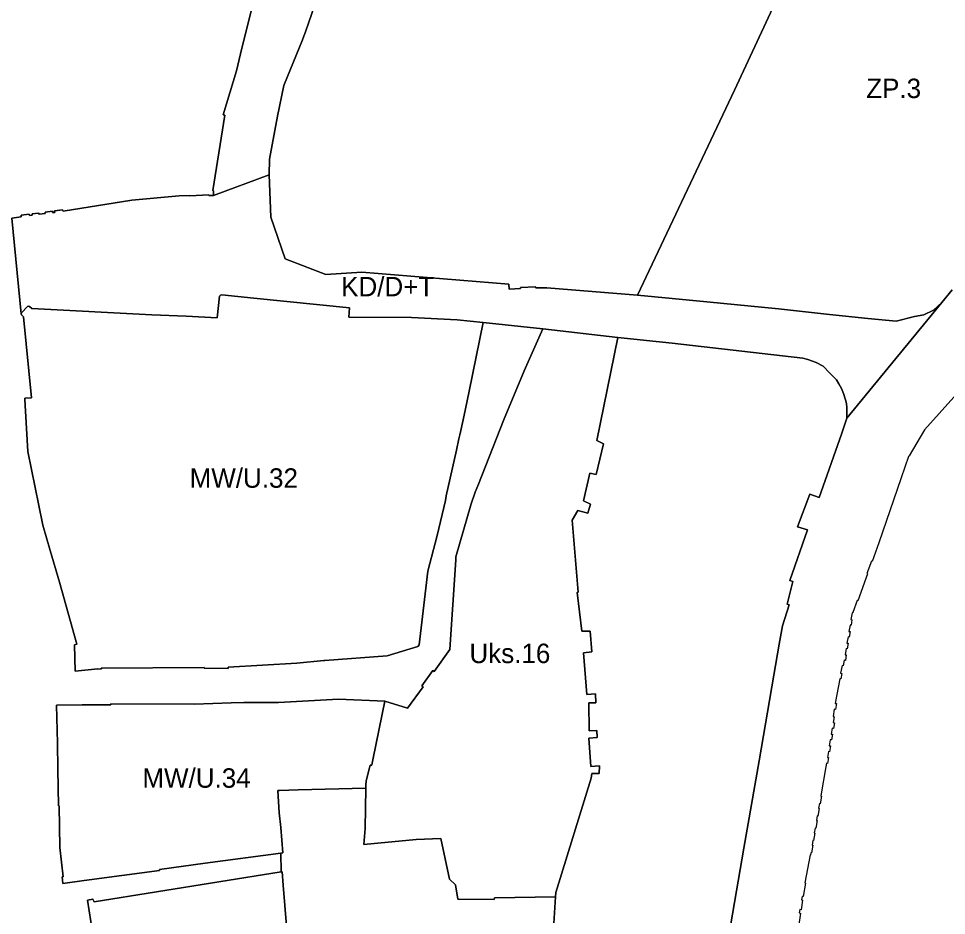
# Model space of a CAD drawing. Extents: x 7423367 to 7424726, y 5546744 to 5548391.
# Drawn here: x 7423955.4 to 7424194.2, y 5547370 to 5547600.8 of the extents above; entities that cross this region are included whole.
import ezdxf

# ---------------------------------------------------------------- set-up
doc = ezdxf.new("R2010")
doc.units = 0
doc.layers.add('linie_rozgraniczajace', color=7, linetype='Continuous')
doc.layers.add('oznaczenia_przeznaczen', color=7, linetype='Continuous')

msp = doc.modelspace()

# ---------------------------------------------------------------- linework, layer by layer
at = {"layer": 'linie_rozgraniczajace'}
for points in [[(7424195.66, 5547530.98), (7424192.95, 5547527.74), (7424190.84, 5547525.79), (7424188.35, 5547524.59), (7424185.9, 5547524.15), (7424181.26, 5547522.91), (7424173.95, 5547523.61), (7424164.06, 5547524.68), (7424150.95, 5547526.11), (7424132.54, 5547527.94), (7424114.69, 5547529.61), (7424122.98, 5547547.25), (7424139.65, 5547582.36), (7424149.46, 5547603.55), (7424164.05, 5547634.41), (7424170.31, 5547647.69), (7424175.4, 5547658.46), (7424181.58, 5547671.67), (7424182.98, 5547674.43), (7424187.08, 5547667.38), (7424194.57, 5547655.72)], [(7424034.47, 5547612.64), (7424029.34, 5547597.71), (7424028.45, 5547595.37), (7424023.69, 5547583.57), (7424022.06, 5547575.71), (7424020.01, 5547564.61), (7424019.9, 5547560.63), (7424005.6, 5547555.3), (7424005.6, 5547556.5), (7424005.44, 5547556.54), (7424008.5, 5547575.97), (7424008.03, 5547576.03), (7424011.47, 5547587.38), (7424012.85, 5547593.23), (7424015.6, 5547604.09)], [(7424149.46, 5547603.55), (7424139.65, 5547582.36), (7424122.98, 5547547.25), (7424114.69, 5547529.61), (7424091.36, 5547531.55), (7424088.52, 5547531.51), (7424088.46, 5547531.79), (7424084.57, 5547531.62), (7424084.6, 5547531.31), (7424081.65, 5547531.19), (7424081.53, 5547532.43), (7424043.78, 5547535.56), (7424034.5, 5547534.91), (7424024.03, 5547538.95), (7424020.34, 5547549.72), (7424019.9, 5547560.63), (7424020.01, 5547564.61), (7424022.06, 5547575.71), (7424023.69, 5547583.57), (7424028.45, 5547595.37), (7424029.34, 5547597.71), (7424034.47, 5547612.64)], [(7424015.6, 5547604.09), (7424012.85, 5547593.23), (7424011.47, 5547587.38), (7424008.03, 5547576.03), (7424008.5, 5547575.97), (7424005.44, 5547556.54), (7424005.6, 5547556.5), (7424005.6, 5547555.3), (7424004.39, 5547555.3), (7424004.38, 5547555.45), (7423999.5, 5547555.18), (7423999.49, 5547555.29), (7423996.74, 5547555.24), (7423984.6, 5547554.11), (7423966.87, 5547551.23), (7423966.76, 5547551.56), (7423964.71, 5547551.31), (7423964.75, 5547550.95), (7423964.17, 5547550.87), (7423964.12, 5547551.22), (7423962.25, 5547550.98), (7423962.29, 5547550.65), (7423960.69, 5547550.44), (7423960.59, 5547550.78), (7423958.88, 5547550.55), (7423958.88, 5547550.2), (7423958.24, 5547550.11), (7423958.15, 5547550.46), (7423956.12, 5547550.19), (7423956.13, 5547549.82), (7423953.67, 5547549.49)], [(7423953.67, 5547549.49), (7423956.05, 5547524.84), (7423956.19, 5547524.54), (7423956.68, 5547524.07), (7423958.72, 5547503.18), (7423958.54, 5547503.18), (7423957.18, 5547503.14), (7423957.03, 5547503.14), (7423957.05, 5547502.74), (7423957.47, 5547495.32), (7423957.8, 5547489.38), (7423961.55, 5547470.88), (7423961.69, 5547470.39), (7423963.52, 5547463.94), (7423965.96, 5547455.79), (7423970.45, 5547439.82), (7423969.78, 5547439.67), (7423970.01, 5547432.86), (7423975.8, 5547433.45), (7423975.8, 5547433.38), (7423976.72, 5547433.46), (7423976.65, 5547433.65), (7424003.15, 5547433.83), (7424003.15, 5547433.63), (7424009.38, 5547433.56), (7424009.37, 5547433.85), (7424027.05, 5547434.91), (7424033.94, 5547435.62), (7424034.18, 5547435.64), (7424050.27, 5547436.84), (7424058.17, 5547439.21), (7424058.48, 5547439.65), (7424060.71, 5547458.62), (7424063.11, 5547467.77), (7424065.23, 5547476.82), (7424065.48, 5547477.95), (7424068.09, 5547489.74), (7424068.74, 5547492.62), (7424068.97, 5547493.65), (7424069.23, 5547494.82), (7424070.07, 5547498.71), (7424070.44, 5547500.39), (7424071.37, 5547504.95), (7424074.96, 5547522.56), (7424090.27, 5547521), (7424085.52, 5547510.17), (7424080.17, 5547497.37), (7424073.72, 5547481.02), (7424072.9, 5547478.96), (7424071.91, 5547475.93), (7424067.96, 5547462.24), (7424067.91, 5547461.55), (7424066.37, 5547438.39), (7424062.33, 5547432.77), (7424062.02, 5547432.99), (7424059.22, 5547429.09), (7424059.48, 5547428.81), (7424055.49, 5547423.29), (7424049.7, 5547425.1), (7424037.73, 5547425.67), (7424022.31, 5547424.81), (7424022.13, 5547424.8), (7424013.42, 5547424.75), (7424010.15, 5547424.73), (7424000.66, 5547424.36), (7423979.15, 5547424.47), (7423979.15, 5547424.22), (7423971.77, 5547424.16), (7423965.22, 5547424.1), (7423965.41, 5547414.3), (7423965.53, 5547407.59), (7423965.7, 5547398.17), (7423965.85, 5547398.17), (7423966.07, 5547387.46), (7423966.88, 5547379.91), (7423966.65, 5547379.91), (7423966.82, 5547378.24), (7423972.3, 5547378.96), (7423991.7, 5547381.53), (7423991.68, 5547381.81), (7424003.43, 5547383.39), (7424022.9, 5547386.01), (7424023.01, 5547381.2), (7423974.87, 5547373.46), (7423974.57, 5547374.13), (7423973.13, 5547373.87), (7423974.91, 5547362.9)], [(7424135.74, 5547350.81), (7424142.07, 5547387.31), (7424145.94, 5547409.81), (7424149.71, 5547431.83), (7424151.1, 5547439.8), (7424151.95, 5547444.55), (7424153.66, 5547449.95), (7424153.17, 5547450.06), (7424154.1, 5547453.83), (7424154.66, 5547455.95), (7424153.82, 5547456.19), (7424158.38, 5547469.22), (7424155.84, 5547470.02), (7424159.03, 5547478.37), (7424161.38, 5547477.58), (7424167.19, 5547493.82), (7424168.25, 5547497.17), (7424168.49, 5547497.94), (7424192.95, 5547527.74), (7424195.66, 5547530.98)], [(7424090.88, 5547332.24), (7424093.59, 5547374.75), (7424093.67, 5547375.89), (7424102.76, 5547405.27), (7424102.96, 5547406.48), (7424104.79, 5547406.48), (7424104.89, 5547408.46), (7424102.68, 5547408.3), (7424102.18, 5547415.64), (7424104.29, 5547415.76), (7424104.21, 5547417.59), (7424102.21, 5547417.49), (7424102.11, 5547424.74), (7424103.94, 5547424.73), (7424103.86, 5547427), (7424101.67, 5547426.83), (7424100.77, 5547437.54), (7424102.88, 5547437.85), (7424102.45, 5547443.16), (7424100.35, 5547443.17), (7424099.12, 5547453.14), (7424099.37, 5547453.18), (7424097.85, 5547471.72), (7424099.28, 5547474.2), (7424101.87, 5547473.53), (7424102.55, 5547475.85), (7424100.77, 5547476.69), (7424102.42, 5547483.79), (7424104.04, 5547483.49), (7424105.88, 5547491.33), (7424104.19, 5547492.25), (7424109.62, 5547518.77), (7424123.56, 5547517.3), (7424157.22, 5547513.42), (7424158.46, 5547513.11), (7424160.68, 5547512.27), (7424162.41, 5547511.32), (7424164.19, 5547509.54), (7424165.84, 5547507.83), (7424166.5, 5547506.78), (7424167.13, 5547505.6), (7424167.66, 5547504.33), (7424168.18, 5547502.73), (7424168.4, 5547501.73), (7424168.51, 5547500.73), (7424168.53, 5547499.53), (7424168.49, 5547497.94), (7424168.25, 5547497.17), (7424167.19, 5547493.82), (7424161.38, 5547477.58), (7424159.03, 5547478.37), (7424155.84, 5547470.02), (7424158.38, 5547469.22), (7424153.82, 5547456.19), (7424154.66, 5547455.95), (7424154.1, 5547453.83), (7424153.17, 5547450.06), (7424153.66, 5547449.95), (7424151.95, 5547444.55), (7424151.1, 5547439.8), (7424149.71, 5547431.83), (7424145.94, 5547409.81), (7424142.07, 5547387.31), (7424135.74, 5547350.81)], [(7424200.59, 5547508.46), (7424188.52, 5547495), (7424184.59, 5547488.28), (7424184.42, 5547488.11), (7424182.5, 5547482.63), (7424176.74, 5547465.86), (7424175.04, 5547461.08), (7424174.84, 5547461.16), (7424173.69, 5547457.97), (7424173.84, 5547457.91), (7424171.36, 5547450.98), (7424171.21, 5547451.03), (7424170.1, 5547447.98), (7424170.07, 5547447.85), (7424169.88, 5547447.88), (7424169.58, 5547446.12), (7424169.85, 5547446.07), (7424169.61, 5547444.65), (7424169.36, 5547444.69), (7424169.08, 5547443.1), (7424169.35, 5547443.05), (7424169.09, 5547441.63), (7424168.83, 5547441.67), (7424168.57, 5547440.1), (7424168.87, 5547440.05), (7424168.64, 5547438.64), (7424168.35, 5547438.69), (7424168.09, 5547437.08), (7424168.38, 5547437.04), (7424168.16, 5547435.61), (7424167.85, 5547435.67), (7424167.59, 5547434.22), (7424167.3, 5547434.28), (7424166.94, 5547432.3), (7424167.2, 5547432.25), (7424166.98, 5547430.86), (7424166.69, 5547430.91), (7424166.37, 5547429.05), (7424165.91, 5547426.38), (7424165.56, 5547424.55), (7424165.85, 5547424.49), (7424165.6, 5547423), (7424165.3, 5547423.05), (7424164.98, 5547421.16), (7424165.29, 5547421.1), (7424165.04, 5547419.64), (7424165.37, 5547419.58), (7424165.11, 5547418.11), (7424164.79, 5547418.17), (7424164.54, 5547416.65), (7424164.85, 5547416.61), (7424164.58, 5547415.14), (7424164.27, 5547415.19), (7424164.02, 5547413.65), (7424164.32, 5547413.6), (7424164.09, 5547412.11), (7424163.79, 5547412.16), (7424163.52, 5547410.64), (7424163.82, 5547410.59), (7424163.58, 5547409.12), (7424163.28, 5547409.18), (7424162.94, 5547407.29), (7424162.01, 5547401.81), (7424161.82, 5547400.71), (7424162.01, 5547400.68), (7424161.67, 5547398.71), (7424161.49, 5547398.75), (7424161.25, 5547397.56), (7424161.45, 5547397.51), (7424161.08, 5547395.56), (7424160.91, 5547395.59), (7424160.7, 5547394.42), (7424160.89, 5547394.39), (7424160.55, 5547392.4), (7424160.37, 5547392.44), (7424160.16, 5547391.22), (7424160.33, 5547391.18), (7424159.97, 5547389.27), (7424159.8, 5547389.29), (7424159.6, 5547388.08), (7424159.76, 5547388.06), (7424159.42, 5547386.07), (7424159.25, 5547386.1), (7424159.18, 5547385.52), (7424159.08, 5547385.54), (7424157.74, 5547378.35), (7424157.89, 5547378.32), (7424157.3, 5547374.82), (7424157.01, 5547374.87), (7424156.86, 5547373.96), (7424157.15, 5547373.91), (7424156.74, 5547371.46), (7424156.45, 5547371.51), (7424156.29, 5547370.61), (7424156.58, 5547370.57), (7424156.11, 5547367.04)], [(7424024.7, 5547363.07), (7424023.54, 5547377.76), (7424023.27, 5547381.24), (7424023.01, 5547381.2), (7424022.9, 5547386.01), (7424023.44, 5547386.08), (7424022.92, 5547392.57), (7424022.48, 5547396.42), (7424022.12, 5547402.14), (7424022.57, 5547402.15), (7424027.36, 5547402.27), (7424044.8, 5547402.7), (7424044.6, 5547392.36), (7424044.24, 5547388.21), (7424057.75, 5547389.56), (7424064.07, 5547389.74), (7424066.27, 5547379.35), (7424067.82, 5547377.85), (7424068.45, 5547374.2), (7424077.82, 5547374.07), (7424077.85, 5547374.54), (7424093.59, 5547374.75), (7424090.88, 5547332.24)]]:
    msp.add_lwpolyline(points, dxfattribs=at)
for points in [[(7423953.67, 5547549.49), (7423956.13, 5547549.82), (7423956.12, 5547550.19), (7423958.15, 5547550.46), (7423958.24, 5547550.11), (7423958.88, 5547550.2), (7423958.88, 5547550.55), (7423960.59, 5547550.78), (7423960.69, 5547550.44), (7423962.29, 5547550.65), (7423962.25, 5547550.98), (7423964.12, 5547551.22), (7423964.17, 5547550.87), (7423964.75, 5547550.95), (7423964.71, 5547551.31), (7423966.76, 5547551.56), (7423966.87, 5547551.23), (7423984.6, 5547554.11), (7423996.74, 5547555.24), (7423999.49, 5547555.29), (7423999.5, 5547555.18), (7424004.38, 5547555.45), (7424004.39, 5547555.3), (7424005.6, 5547555.3), (7424019.9, 5547560.63), (7424020.34, 5547549.72), (7424024.03, 5547538.95), (7424034.5, 5547534.91), (7424043.78, 5547535.56), (7424081.53, 5547532.43), (7424081.65, 5547531.19), (7424084.6, 5547531.31), (7424084.57, 5547531.62), (7424088.46, 5547531.79), (7424088.52, 5547531.51), (7424091.36, 5547531.55), (7424114.69, 5547529.61), (7424132.54, 5547527.94), (7424150.95, 5547526.11), (7424164.06, 5547524.68), (7424173.95, 5547523.61), (7424181.26, 5547522.91), (7424185.9, 5547524.15), (7424188.35, 5547524.59), (7424190.84, 5547525.79), (7424192.95, 5547527.74), (7424168.49, 5547497.94), (7424168.53, 5547499.53), (7424168.51, 5547500.73), (7424168.4, 5547501.73), (7424168.18, 5547502.73), (7424167.66, 5547504.33), (7424167.13, 5547505.6), (7424166.5, 5547506.78), (7424165.84, 5547507.83), (7424164.19, 5547509.54), (7424162.41, 5547511.32), (7424160.68, 5547512.27), (7424158.46, 5547513.11), (7424157.22, 5547513.42), (7424123.56, 5547517.3), (7424109.62, 5547518.77), (7424090.27, 5547521), (7424074.96, 5547522.56), (7424068.3, 5547523.26), (7424056.56, 5547523.87), (7424040.43, 5547524), (7424040.56, 5547526.39), (7424015.99, 5547528.86), (7424007.7, 5547529.74), (7424007.38, 5547529.65), (7424007.16, 5547529.38), (7424006.5, 5547523.83), (7423998.58, 5547524.25), (7423989.71, 5547524.59), (7423958.81, 5547526.17), (7423958.27, 5547526.69), (7423957.97, 5547526.8), (7423957.69, 5547526.68), (7423956.18, 5547525.12), (7423956.05, 5547524.84)], [(7423956.05, 5547524.84), (7423956.18, 5547525.12), (7423957.69, 5547526.68), (7423957.97, 5547526.8), (7423958.27, 5547526.69), (7423958.81, 5547526.17), (7423989.71, 5547524.59), (7423998.58, 5547524.25), (7424006.5, 5547523.83), (7424007.16, 5547529.38), (7424007.38, 5547529.65), (7424007.7, 5547529.74), (7424015.99, 5547528.86), (7424040.56, 5547526.39), (7424040.43, 5547524), (7424056.56, 5547523.87), (7424068.3, 5547523.26), (7424074.96, 5547522.56), (7424071.37, 5547504.95), (7424070.44, 5547500.39), (7424070.07, 5547498.71), (7424069.23, 5547494.82), (7424068.97, 5547493.65), (7424068.74, 5547492.62), (7424068.09, 5547489.74), (7424065.48, 5547477.95), (7424065.23, 5547476.82), (7424063.11, 5547467.77), (7424060.71, 5547458.62), (7424058.48, 5547439.65), (7424058.17, 5547439.21), (7424050.27, 5547436.84), (7424034.18, 5547435.64), (7424033.94, 5547435.62), (7424027.05, 5547434.91), (7424009.37, 5547433.85), (7424009.38, 5547433.56), (7424003.15, 5547433.63), (7424003.15, 5547433.83), (7423976.65, 5547433.65), (7423976.72, 5547433.46), (7423975.8, 5547433.38), (7423975.8, 5547433.45), (7423970.01, 5547432.86), (7423969.78, 5547439.67), (7423970.45, 5547439.82), (7423965.96, 5547455.79), (7423963.52, 5547463.94), (7423961.69, 5547470.39), (7423961.55, 5547470.88), (7423957.8, 5547489.38), (7423957.47, 5547495.32), (7423957.05, 5547502.74), (7423957.03, 5547503.14), (7423957.18, 5547503.14), (7423958.54, 5547503.18), (7423958.72, 5547503.18), (7423956.68, 5547524.07), (7423956.19, 5547524.54)], [(7424044.24, 5547388.21), (7424044.6, 5547392.36), (7424044.8, 5547402.7), (7424044.74, 5547403.49), (7424044.89, 5547404.64), (7424045.72, 5547407.94), (7424045.9, 5547408.63), (7424046.33, 5547408.64), (7424046.43, 5547409.18), (7424046.7, 5547410.47), (7424049.7, 5547425.1), (7424055.49, 5547423.29), (7424059.48, 5547428.81), (7424059.22, 5547429.09), (7424062.02, 5547432.99), (7424062.33, 5547432.77), (7424066.37, 5547438.39), (7424067.91, 5547461.55), (7424067.96, 5547462.24), (7424071.91, 5547475.93), (7424072.9, 5547478.96), (7424073.72, 5547481.02), (7424080.17, 5547497.37), (7424085.52, 5547510.17), (7424090.27, 5547521), (7424109.62, 5547518.77), (7424104.19, 5547492.25), (7424105.88, 5547491.33), (7424104.04, 5547483.49), (7424102.42, 5547483.79), (7424100.77, 5547476.69), (7424102.55, 5547475.85), (7424101.87, 5547473.53), (7424099.28, 5547474.2), (7424097.85, 5547471.72), (7424099.37, 5547453.18), (7424099.12, 5547453.14), (7424100.35, 5547443.17), (7424102.45, 5547443.16), (7424102.88, 5547437.85), (7424100.77, 5547437.54), (7424101.67, 5547426.83), (7424103.86, 5547427), (7424103.94, 5547424.73), (7424102.11, 5547424.74), (7424102.21, 5547417.49), (7424104.21, 5547417.59), (7424104.29, 5547415.76), (7424102.18, 5547415.64), (7424102.68, 5547408.3), (7424104.89, 5547408.46), (7424104.79, 5547406.48), (7424102.96, 5547406.48), (7424102.76, 5547405.27), (7424093.67, 5547375.89), (7424093.59, 5547374.75), (7424077.85, 5547374.54), (7424077.82, 5547374.07), (7424068.45, 5547374.2), (7424067.82, 5547377.85), (7424066.27, 5547379.35), (7424064.07, 5547389.74), (7424057.75, 5547389.56)], [(7423966.07, 5547387.46), (7423965.85, 5547398.17), (7423965.7, 5547398.17), (7423965.53, 5547407.59), (7423965.41, 5547414.3), (7423965.22, 5547424.1), (7423971.77, 5547424.16), (7423979.15, 5547424.22), (7423979.15, 5547424.47), (7424000.66, 5547424.36), (7424010.15, 5547424.73), (7424013.42, 5547424.75), (7424022.13, 5547424.8), (7424022.31, 5547424.81), (7424037.73, 5547425.67), (7424049.7, 5547425.1), (7424046.7, 5547410.47), (7424046.43, 5547409.18), (7424046.33, 5547408.64), (7424045.9, 5547408.63), (7424045.72, 5547407.94), (7424044.89, 5547404.64), (7424044.74, 5547403.49), (7424044.8, 5547402.7), (7424027.36, 5547402.27), (7424022.57, 5547402.15), (7424022.12, 5547402.14), (7424022.48, 5547396.42), (7424022.92, 5547392.57), (7424023.44, 5547386.08), (7424022.9, 5547386.01), (7424003.43, 5547383.39), (7423991.68, 5547381.81), (7423991.7, 5547381.53), (7423972.3, 5547378.96), (7423966.82, 5547378.24), (7423966.65, 5547379.91), (7423966.88, 5547379.91)], [(7423973.13, 5547373.87), (7423974.57, 5547374.13), (7423974.87, 5547373.46), (7424023.01, 5547381.2), (7424023.27, 5547381.24), (7424023.54, 5547377.76), (7424024.7, 5547363.07), (7424025.62, 5547351.34), (7424018.6, 5547350.49), (7424005.17, 5547349.22), (7424004.44, 5547349.15), (7424004.48, 5547348.87), (7424002.72, 5547348.68), (7423994.96, 5547347.87), (7423995.06, 5547347.15), (7423978.05, 5547344.11), (7423976.14, 5547354.78), (7423974.91, 5547362.9)]]:
    msp.add_lwpolyline(points, close=True, dxfattribs=at)

# ---------------------------------------------------------------- texts
at = {"layer": 'oznaczenia_przeznaczen'}
for s, p in [('ZP.3', (7424173.51, 5547580.36)), ('KD/D+T', (7424038.42, 5547529.34)), ('MW/U.32', (7423999.44, 5547480.06)), ('Uks.16', (7424071.43, 5547434.93)), ('MW/U.34', (7423987.28, 5547402.85))]:
    msp.add_text(s, height=5, dxfattribs=at).set_placement(p)

doc.saveas('drawing.dxf')
